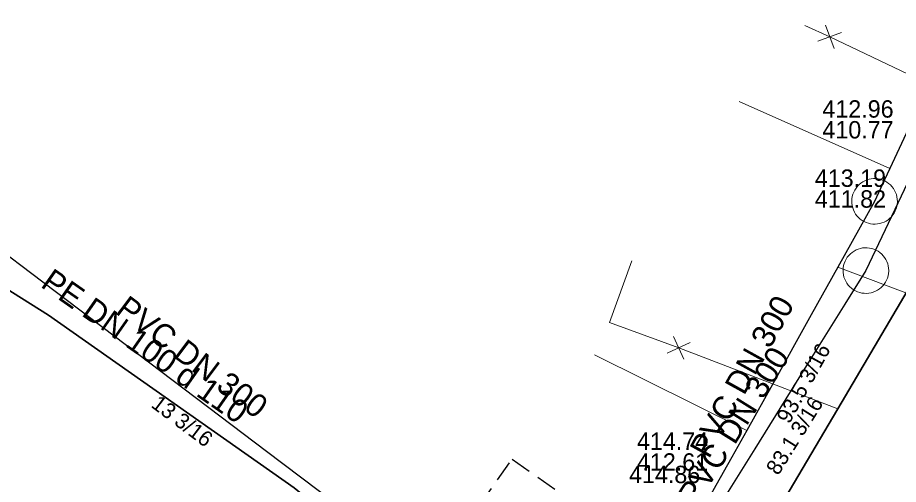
# Model space of a CAD drawing. Extents: x -772952 to -772403, y -1033777 to -1033210.
# Drawn here: x -772900.62 to -772855.07, y -1033556.43 to -1033532.28 of the extents above; entities that cross this region are included whole.
import ezdxf

# ---------------------------------------------------------------- set-up
doc = ezdxf.new("R2010")
doc.units = 0
doc.header["$LTSCALE"] = 0.36
doc.linetypes.add('MEDIUM_DASHED', pattern=[4.5, 3, -1.5])
for name, color, linetype, lineweight in [('15', 7, 'Continuous', 13), ('16', 7, 'Continuous', 35), ('2', 7, 'Continuous', 25), ('24', 7, 'MEDIUM_DASHED', 25), ('4', 7, 'Continuous', 13), ('57', 7, 'Continuous', 13), ('59', 7, 'Continuous', 13)]:
    doc.layers.add(name, color=color, linetype=linetype, lineweight=lineweight)
for name, color, linetype in [('17', 7, 'Continuous'), ('3', 7, 'Continuous'), ('6', 7, 'Continuous')]:
    doc.layers.add(name, color=color, linetype=linetype)

msp = doc.modelspace()

# ---------------------------------------------------------------- linework, layer by layer
at = {"layer": '15'}
for p, q in [((-772858.398, -1033533.884), (-772858.841, -1033532.672)), ((-772858.01, -1033533.055), (-772859.232, -1033533.505)), ((-772866.161, -1033549.955), (-772866.698, -1033548.781)), ((-772865.839, -1033549.098), (-772867.022, -1033549.642))]:
    msp.add_line(p, q, dxfattribs=at)
at = {"layer": '16'}
for points in [[(-772870.403, -1033572.723), (-772865.918, -1033565.594), (-772858.208, -1033552.52), (-772854.394, -1033546.056), (-772851.153, -1033540.157), (-772849.795, -1033537.486), (-772845.024, -1033528.103), (-772839.019, -1033515.318), (-772837.765, -1033512.662), (-772833.548, -1033502.146)], [(-772871.79, -1033565.033), (-772876.199, -1033564.929), (-772886.309, -1033556.62), (-772899.019, -1033547.67), (-772902.3, -1033545.62), (-772906.89, -1033544.059), (-772909.76, -1033543.28), (-772913.98, -1033542.55), (-772915.23, -1033542.289), (-772915.48, -1033542.21)]]:
    msp.add_lwpolyline(points, dxfattribs=at)
at = {"layer": '2'}
for points in [[(-772834.78, -1033495.6), (-772836.114, -1033498.463), (-772837.51, -1033501.461), (-772838.768, -1033504.161), (-772840.12, -1033507.062), (-772842.931, -1033513.095), (-772845.54, -1033518.695), (-772849.358, -1033526.891), (-772852.073, -1033532.717), (-772853.674, -1033536.155), (-772854.426, -1033537.769), (-772855.508, -1033540.092), (-772855.782, -1033540.679), (-772856.3, -1033541.79)], [(-772834.12, -1033497.489), (-772836.663, -1033502.872), (-772837.696, -1033505.057), (-772838.705, -1033507.192), (-772840.489, -1033510.965), (-772843.322, -1033516.96), (-772845.177, -1033520.885), (-772847.84, -1033526.52), (-772850.14, -1033531.386), (-772853.138, -1033537.728), (-772854.606, -1033540.835), (-772856.75, -1033545.37)], [(-772872.43, -1033566.313), (-772887.748, -1033554.729), (-772899.887, -1033545.543), (-772908.093, -1033539.332), (-772910.4, -1033537.587)], [(-772856.3, -1033541.79), (-772858.202, -1033545.2), (-772859.574, -1033547.659), (-772861.584, -1033551.262), (-772862.915, -1033553.648), (-772863.687, -1033555.031), (-772864.505, -1033556.497), (-772865.89, -1033558.98)], [(-772856.75, -1033545.37), (-772857.835, -1033547.112), (-772858.191, -1033547.661), (-772859.727, -1033550.149), (-772861.201, -1033552.516), (-772862.495, -1033554.592), (-772863.958, -1033556.941), (-772866.3, -1033560.7)]]:
    msp.add_lwpolyline(points, dxfattribs=at)
at = {"layer": '24'}
msp.add_lwpolyline([(-772872.201, -1033557.331), (-772873.797, -1033559.595), (-772876.732, -1033557.521), (-772875.043, -1033555.127), (-772872.485, -1033556.935), (-772872.577, -1033557.066)], close=True, dxfattribs=at)
at = {"layer": '4'}
for points in [[(-772855.12, -1033541.79), (-772855.126, -1033541.671), (-772855.144, -1033541.554), (-772855.173, -1033541.438), (-772855.214, -1033541.327), (-772855.266, -1033541.22), (-772855.329, -1033541.119), (-772855.402, -1033541.024), (-772855.483, -1033540.938), (-772855.573, -1033540.86), (-772855.671, -1033540.791), (-772855.774, -1033540.733), (-772855.883, -1033540.686), (-772855.997, -1033540.649), (-772856.113, -1033540.624), (-772856.231, -1033540.612), (-772856.35, -1033540.611), (-772856.469, -1033540.622), (-772856.585, -1033540.645), (-772856.699, -1033540.679), (-772856.809, -1033540.725), (-772856.914, -1033540.782), (-772857.012, -1033540.849), (-772857.103, -1033540.925), (-772857.186, -1033541.01), (-772857.26, -1033541.104), (-772857.324, -1033541.204), (-772857.378, -1033541.31), (-772857.421, -1033541.421), (-772857.453, -1033541.535), (-772857.472, -1033541.653), (-772857.48, -1033541.772), (-772857.476, -1033541.89), (-772857.46, -1033542.008), (-772857.432, -1033542.124), (-772857.393, -1033542.236), (-772857.342, -1033542.344), (-772857.281, -1033542.446), (-772857.21, -1033542.542), (-772857.13, -1033542.629), (-772857.041, -1033542.709), (-772856.945, -1033542.779), (-772856.842, -1033542.839), (-772856.734, -1033542.888), (-772856.621, -1033542.926), (-772856.505, -1033542.952), (-772856.387, -1033542.967), (-772856.268, -1033542.97), (-772856.15, -1033542.961), (-772856.032, -1033542.94), (-772855.918, -1033542.907), (-772855.808, -1033542.863), (-772855.702, -1033542.808), (-772855.603, -1033542.742), (-772855.51, -1033542.667), (-772855.426, -1033542.583), (-772855.351, -1033542.491), (-772855.285, -1033542.392), (-772855.229, -1033542.287), (-772855.185, -1033542.177), (-772855.151, -1033542.063), (-772855.13, -1033541.946), (-772855.12, -1033541.827)], [(-772855.57, -1033545.37), (-772855.576, -1033545.251), (-772855.594, -1033545.134), (-772855.623, -1033545.018), (-772855.664, -1033544.907), (-772855.716, -1033544.8), (-772855.779, -1033544.699), (-772855.852, -1033544.604), (-772855.933, -1033544.518), (-772856.023, -1033544.44), (-772856.121, -1033544.371), (-772856.224, -1033544.313), (-772856.333, -1033544.266), (-772856.447, -1033544.229), (-772856.563, -1033544.204), (-772856.681, -1033544.192), (-772856.8, -1033544.191), (-772856.919, -1033544.202), (-772857.035, -1033544.225), (-772857.149, -1033544.259), (-772857.259, -1033544.305), (-772857.364, -1033544.362), (-772857.462, -1033544.429), (-772857.553, -1033544.505), (-772857.636, -1033544.59), (-772857.71, -1033544.684), (-772857.774, -1033544.784), (-772857.828, -1033544.89), (-772857.871, -1033545.001), (-772857.903, -1033545.115), (-772857.922, -1033545.233), (-772857.93, -1033545.352), (-772857.926, -1033545.47), (-772857.91, -1033545.588), (-772857.882, -1033545.704), (-772857.843, -1033545.816), (-772857.792, -1033545.924), (-772857.731, -1033546.026), (-772857.66, -1033546.122), (-772857.58, -1033546.209), (-772857.491, -1033546.289), (-772857.395, -1033546.359), (-772857.292, -1033546.419), (-772857.184, -1033546.468), (-772857.071, -1033546.506), (-772856.955, -1033546.532), (-772856.837, -1033546.547), (-772856.718, -1033546.55), (-772856.6, -1033546.541), (-772856.482, -1033546.52), (-772856.368, -1033546.487), (-772856.258, -1033546.443), (-772856.152, -1033546.388), (-772856.053, -1033546.322), (-772855.96, -1033546.247), (-772855.876, -1033546.163), (-772855.801, -1033546.071), (-772855.735, -1033545.972), (-772855.679, -1033545.867), (-772855.635, -1033545.757), (-772855.601, -1033545.643), (-772855.58, -1033545.526), (-772855.57, -1033545.407)]]:
    msp.add_lwpolyline(points, close=True, dxfattribs=at)
at = {"layer": '57'}
for p, q in [((-772855.508, -1033540.092), (-772863.31, -1033536.63)), ((-772858.202, -1033545.2), (-772848.39, -1033548.89)), ((-772862.915, -1033553.648), (-772870.78, -1033549.73))]:
    msp.add_line(p, q, dxfattribs=at)
at = {"layer": '59'}
for points in [[(-772849.795, -1033537.486), (-772858.62, -1033533.28), (-772859.9, -1033532.69)], [(-772858.208, -1033552.52), (-772866.43, -1033549.37), (-772870, -1033548.05), (-772868.85, -1033544.87)]]:
    msp.add_lwpolyline(points, dxfattribs=at)

# ---------------------------------------------------------------- texts
at = {"layer": '17'}
msp.add_text('PE DN 100 d 110 ', height=1.2, rotation=325, dxfattribs=at).set_placement((-772899.481, -1033546.185))
at = {"layer": '3'}
for s, height, rotation, p in [('PVC DN 300', 1.2, 323, (-772895.614, -1033547.554)), ('PVC DN 300', 1.2, 61, (-772864.867, -1033555.151)), ('93.5 3/16', 0.8, 61, (-772860.712, -1033553.343)), ('PVC DN 300', 1.2, 58, (-772865.52, -1033557.613)), ('13 3/16', 0.8, 323, (-772893.762, -1033552.4)), ('83.1 3/16', 0.8, 58, (-772861.284, -1033556.01))]:
    msp.add_text(s, height=height, rotation=rotation, dxfattribs=at).set_placement(p)
at = {"layer": '6'}
for s, p in [('412.96', (-772858.998, -1033537.458)), ('410.77', (-772858.998, -1033538.535)), ('413.19', (-772859.39, -1033541.039)), ('411.82', (-772859.39, -1033542.116)), ('414.74', (-772868.588, -1033554.647)), ('412.61', (-772868.588, -1033555.724)), ('414.86', (-772868.998, -1033556.369))]:
    msp.add_text(s, height=0.9, dxfattribs=at).set_placement(p)

doc.saveas('drawing.dxf')
